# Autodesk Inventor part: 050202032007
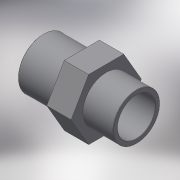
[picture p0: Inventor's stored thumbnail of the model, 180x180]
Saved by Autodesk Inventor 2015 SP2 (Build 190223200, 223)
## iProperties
Created: 2017-10
Part Number: 050202032007
Material: Generic
Description: PLASSON REDUCER THR-CEM PVC 32(25)3/4"F
Document SubType Name: Modeling
Designer: KIM
Density: 1 g/cm^3
Appearance: Default
Author: KIM
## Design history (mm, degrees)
derived "050202.ipt"
feature "Solid1::050202.ipt"
tag "TaggingFeature1"
body "Solid1"
other parameters: "d1" = 25, "d2" = 36, "d3" = 24.117, "d4" = 22.5, "d6" = 18, "d7" = 32, "d8" = 28.75, "d13" = 0, "d14" = 0.25, "d16" = 12, "d17" = 22, "d18" = 21.6, "d_" = 25, "G_" = 24.117, "C_" = 36, "B_" = 12, "L_" = 22, "lt_" = 18, "D_" = 32
